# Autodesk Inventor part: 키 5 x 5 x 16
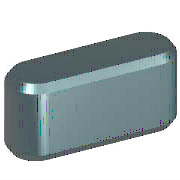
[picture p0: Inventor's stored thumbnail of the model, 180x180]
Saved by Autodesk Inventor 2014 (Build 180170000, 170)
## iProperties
IsCustomPart: 1
Created: 2012-02
Part Number: 키 5 x 5 x 16
Material: 강철, 연강
Description: 키 및 해당 키홈
Document SubType Name: Modeling
Standard: KS B 1311
Designer: mduedu
Standards Organization: KS
Language: ko-KR
Size Designation: 5 x 5 x 16
Categories: <MemberInstance><Categories><Category DisplayName="샤프트 부품" InternalName="7f7aeb1f-a693-4053-b835-cee3144e0d98" Mnemonic="SHFT"><Category DisplayName="키" Interna
Density: 1 g/cm^3
Appearance: Yellow
Author: mduedu
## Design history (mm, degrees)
sketch "스케치1"
  geometry: L1 (2.5, 2.5)-(11.5, 2.5); L2 (11.5, -2.5)-(2.5, -2.5); L3 (0, 8.9)-(0, -4.4) reference; L4 (-3.2, 0)-(19.2, 0) reference; L5 (14, 0)-(14, 7); A1 r 2.5 centre (2.5, 0) between (2.5, 2.5) and (2.5, -2.5); A2 r 2.5 centre (11.5, 0) between (11.5, -2.5) and (11.5, 2.5)
  constraints: 6 end point, 5 point on circle, 4 tangent, 3 point on line, 2 centre point, 1 horizontal, 1 parallel, 1 perpendicular
  dimensions: "d0" = 2.5 radius of A1 (= 0.5 x PB); "d13" = 2.5 radius of A2 (= 0.5 x PB); "d14" = 14 distance between parallel lines of L5 L3 (= NLG)
extrude "본체1" new body sketch "스케치1" taper "d3" = 0 deg; stored distance "d4" = 10
workplane "Work Plane3"
body "Solid1"
workplane "Work Plane1"
workplane "Work Plane2"
chamfer "모따기1" distance "d8" = 0.4 (= PHH); stored, may be unused: second distance "d9" = 0.4 (= PHH), angle "d15" = 45 deg
other parameters: "d1" = -3 (= -PNT), "d2" = 2 (= PH - PNT), "NLG" = 14 [user parameter; used in 3 equation terms], "PB" = 5 [user parameter; used in 2 equation terms], "PNT" = 3 [user parameter; used in 2 equation terms], "PH" = 5 [user parameter; used in 1 equation term], "PHH" = 0.4 [user parameter; used in 2 equation terms], "d10" = 0, "d16" = 0, "d17" = 0, "d18" = 0, "WDMIN" = 12 [user parameter], "PLB2" = 14 (= NLG) [user parameter], "WDMAX" = 17 [user parameter], "PLB1" = 14 (= NLG) [user parameter], "RR" = 0.16 [user parameter], "PUEB" = 2.3 [user parameter]
